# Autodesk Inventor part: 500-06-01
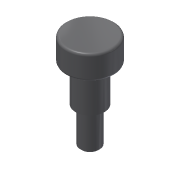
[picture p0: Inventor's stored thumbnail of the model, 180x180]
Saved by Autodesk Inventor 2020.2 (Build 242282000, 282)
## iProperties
Created: 2015-10
Part Number: 500-06-01
Material: Stal
Document SubType Name: Modeling
Designer: F.Stasiak
Density: 7.85 g/cm^3
Appearance: Płyta
Description: Rolka
Manager: www.cadconsulting.pl
Company: Fabian Stasiak CAD Consulting
Author: F.Stasiak
Subject: Zbiór ćwiczeń. Autodesk Inventor 2020. Kurs podstawowy
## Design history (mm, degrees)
sketch "Szkic1"
  geometry: C1 r 20 at (0, 0); 1 further point
  constraints: 1 centre point, 1 coincident
  dimensions: "d0" = 40 diameter of C1
extrude "Wyciągnięcie proste1" new body sketch "Szkic1" distance "d1" = 150; taper "d2" = 0 deg
sketch "Szkic2"
  geometry: C1 r 20 at (0, 0) reference; C2 r 50 at (0, 0)
  constraints: 1 centre point, 1 coincident
  dimensions: "d3" = 100 diameter of C2
extrude "Wyciągnięcie proste2" join sketch "Szkic2" distance "d4" = 50; taper "d5" = 0 deg
sketch "Szkic3"
  geometry: C1 r 20 at (0, 0) reference; C2 r 20 at (0, 0) reference; C3 r 30 at (0, 0)
  constraints: 1 centre point, 1 coincident
  dimensions: "d6" = 60 diameter of C3
extrude "Wyciągnięcie proste3" join sketch "Szkic3" distance "d7" = 75; taper "d8" = 0 deg
fillet "Zaokrąglenie1" dims "d9" = 5
chamfer "Faza1" distance "d10" = 3; stored, may be unused: second distance "d11" = 2, angle "d12" = 45 deg
node "Bryła1"
